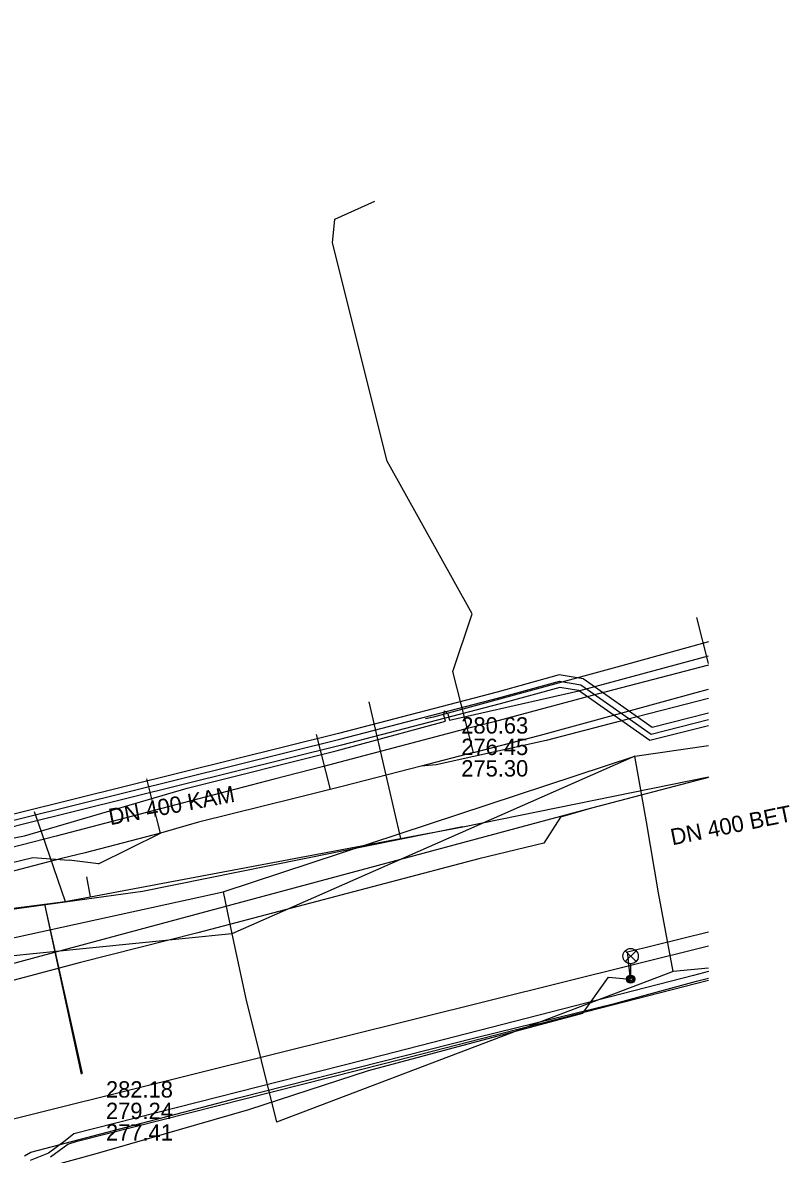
# Model space of a CAD drawing. Extents: x -599854 to -599675, y -1160809 to -1160543.
# Drawn here: x -599712.8 to -599675.3, y -1160609.7 to -1160554.4 of the extents above; entities that cross this region are included whole.
import ezdxf

# ---------------------------------------------------------------- set-up
doc = ezdxf.new("R2010")
doc.units = 0
for name, color, linetype in [('BKOM-ODVODNENI_trasa sítě', 7, 'Continuous'), ('BVK-JEDNOTNA_popisy', 7, 'Continuous'), ('BVK-JEDNOTNA_trasa sítě', 7, 'Continuous'), ('BVK-KANALIZACE_ vyřazená trasa sítě', 7, 'Continuous'), ('BVK-VODOVOD_trasa sítě', 7, 'Continuous'), ('BVK-VODOVOD_trasa zrušené sítě', 7, 'Continuous'), ('CETIN_kabel podzemní', 7, 'Continuous'), ('DESTOVA_trasa neprovozované sítě', 7, 'Continuous'), ('DPMB_kabel', 7, 'Continuous'), ('DPMB_kyneta', 7, 'Continuous'), ('DPMB_trolejové vedení-nosné lano', 7, 'Continuous'), ('DSP-JEDNOTNA-BVK_trasa sítě', 7, 'Continuous'), ('EON-NN_kabel', 7, 'Continuous'), ('EON-VN_kabel', 7, 'Continuous'), ('INNOGY-STL_trasa sítě', 7, 'Continuous'), ('JEDNOTNA_trasa neprovozované sítě', 7, 'Continuous'), ('QUANTCOM_kabel', 7, 'Continuous'), ('TSB_kabel VO', 7, 'Continuous'), ('TSB_lampy VO', 7, 'Continuous')]:
    doc.layers.add(name, color=color, linetype=linetype)

msp = doc.modelspace()

# ---------------------------------------------------------------- linework, layer by layer
at = {"layer": 'BKOM-ODVODNENI_trasa sítě'}
for points in [[(-599728.85, -1160599.72), (-599710.68, -1160597.38)], [(-599709.827, -1160605.79), (-599711.67, -1160597.51)]]:
    msp.add_lwpolyline(points, dxfattribs=at)
at = {"layer": 'BVK-JEDNOTNA_popisy'}
for p, q in [((-599691.309, -1160589.819), (-599691.309, -1160589.819)), ((-599708.68, -1160607.611), (-599708.68, -1160607.611))]:
    msp.add_line(p, q, dxfattribs=at)
at = {"layer": 'BVK-JEDNOTNA_trasa sítě'}
msp.add_line((-599691.23, -1160593.72), (-599679.2237, -1160591.2908), dxfattribs=at)
msp.add_lwpolyline([(-599710.68, -1160597.38), (-599709.45, -1160597.149), (-599694.277, -1160594.293), (-599691.23, -1160593.72)], dxfattribs=at)
at = {"layer": 'BVK-KANALIZACE_ vyřazená trasa sítě'}
for p, q in [((-599706.89, -1160596.87), (-599691.244, -1160593.711)), ((-599747.65, -1160602.53), (-599706.89, -1160596.87))]:
    msp.add_line(p, q, dxfattribs=at)
at = {"layer": 'BVK-VODOVOD_trasa sítě'}
msp.add_line((-599679.2237, -1160585.7449), (-599679.795, -1160583.492), dxfattribs=at)
for points in [[(-599679.2237, -1160591.3119), (-599684.94, -1160592.81)], [(-599684.94, -1160592.81), (-599686.46, -1160593.25), (-599687.27, -1160594.52), (-599690.45, -1160595.29), (-599704.19, -1160598.9), (-599709.92, -1160600.36), (-599718.2, -1160602.56), (-599719.28, -1160602.87), (-599719.633, -1160602.967)]]:
    msp.add_lwpolyline(points, dxfattribs=at)
at = {"layer": 'BVK-VODOVOD_trasa zrušené sítě'}
for points in [[(-599684.94, -1160592.81), (-599720.55, -1160602.37), (-599722.14, -1160601.43), (-599723.128, -1160597.158), (-599723.241, -1160596.669)], [(-599679.2237, -1160599.5579), (-599732.933, -1160612.912), (-599785.657, -1160621.012)]]:
    msp.add_lwpolyline(points, dxfattribs=at)
at = {"layer": 'CETIN_kabel podzemní'}
for points in [[(-599690.71, -1160590.1), (-599691.73, -1160586.14), (-599690.78, -1160583.31), (-599694.94, -1160575.86), (-599697.61, -1160565.18), (-599697.49, -1160564.02), (-599695.54, -1160563.15)], [(-599747.4, -1160585.47), (-599742.37, -1160594.32), (-599740.56, -1160595.49), (-599738.44, -1160596.21), (-599736.55, -1160596.84), (-599734.39, -1160596.99), (-599728.89, -1160596.5), (-599727.72, -1160596.19), (-599723.67, -1160595.52), (-599720.71, -1160596.76), (-599718.38, -1160596.71), (-599712.25, -1160595.23), (-599710.48, -1160595.36)], [(-599690.71, -1160590.1), (-599687.5, -1160589.27), (-599683.69, -1160588.22), (-599679.83, -1160587.16), (-599679.2237, -1160586.9936)], [(-599679.2237, -1160587.4478), (-599683.28, -1160588.5), (-599687.16, -1160589.5), (-599692.53, -1160590.69), (-599693.27, -1160590.76)], [(-599698.4, -1160589.21), (-599697.72, -1160591.9)], [(-599690.71, -1160590.1), (-599693.27, -1160590.76)], [(-599693.27, -1160590.76), (-599697.14, -1160591.76), (-599697.72, -1160591.9)], [(-599706.2, -1160593.33), (-599706.69, -1160591.38)], [(-599697.72, -1160591.9), (-599699.35, -1160592.31)], [(-599699.35, -1160592.31), (-599704.15, -1160593.5), (-599706.01, -1160594.04)], [(-599706.01, -1160594.04), (-599706.2, -1160593.33)], [(-599706.01, -1160594.04), (-599709.69, -1160594.99)], [(-599709.04, -1160595.54), (-599706.01, -1160594.04)], [(-599709.69, -1160594.99), (-599710.85, -1160595.28)], [(-599710.85, -1160595.28), (-599714.54, -1160596.23), (-599714.84, -1160596.6)], [(-599709.04, -1160595.54), (-599710.48, -1160595.36)]]:
    msp.add_lwpolyline(points, dxfattribs=at)
at = {"layer": 'DESTOVA_trasa neprovozované sítě'}
for p, q in [((-599709.635, -1160596.166), (-599709.45, -1160597.149)), ((-599709.87, -1160605.81), (-599711.672, -1160597.508))]:
    msp.add_line(p, q, dxfattribs=at)
msp.add_lwpolyline([(-599728.85, -1160599.72), (-599711.672, -1160597.508), (-599710.68, -1160597.38)], dxfattribs=at)
at = {"layer": 'DPMB_kabel'}
for points in [[(-599679.2237, -1160588.1676), (-599681.97, -1160588.865), (-599685.344, -1160586.495), (-599686.527, -1160586.303), (-599689.558, -1160587.14), (-599697.314, -1160589.159), (-599712.863, -1160593.019), (-599718.483, -1160594.441), (-599721.294, -1160594.539), (-599722.781, -1160593.351), (-599724.035, -1160587.852), (-599724.405, -1160585.594), (-599725.644, -1160579.901), (-599728.628, -1160572.9), (-599732.573, -1160567.596), (-599737.293, -1160564.609), (-599740.184, -1160563.956), (-599742.967, -1160562.458), (-599745.93, -1160559.394)], [(-599679.2237, -1160588.1676), (-599681.97, -1160588.865), (-599685.344, -1160586.495), (-599686.527, -1160586.303), (-599689.558, -1160587.14), (-599697.314, -1160589.159), (-599712.863, -1160593.019), (-599718.483, -1160594.441), (-599721.294, -1160594.539), (-599722.781, -1160593.351), (-599724.035, -1160587.852), (-599724.405, -1160585.594), (-599725.644, -1160579.901), (-599728.628, -1160572.9), (-599732.573, -1160567.596), (-599737.293, -1160564.609), (-599740.184, -1160563.956), (-599742.967, -1160562.458), (-599745.93, -1160559.394)], [(-599746.11, -1160559.64), (-599743.15, -1160562.7), (-599740.29, -1160564.24), (-599737.41, -1160564.89), (-599732.78, -1160567.82), (-599728.89, -1160573.05), (-599725.931, -1160579.993), (-599724.7, -1160585.65), (-599724.33, -1160587.91), (-599723.05, -1160593.52), (-599721.395, -1160594.843), (-599718.44, -1160594.74), (-599712.79, -1160593.31), (-599697.24, -1160589.45), (-599689.48, -1160587.43), (-599686.51, -1160586.61), (-599685.46, -1160586.78), (-599682.03, -1160589.19), (-599679.2237, -1160588.477)], [(-599746.11, -1160559.64), (-599743.15, -1160562.7), (-599740.29, -1160564.24), (-599737.41, -1160564.89), (-599732.78, -1160567.82), (-599728.89, -1160573.05), (-599725.931, -1160579.993), (-599724.7, -1160585.65), (-599724.33, -1160587.91), (-599723.05, -1160593.52), (-599721.395, -1160594.843), (-599718.44, -1160594.74), (-599712.79, -1160593.31), (-599697.24, -1160589.45), (-599689.48, -1160587.43), (-599686.51, -1160586.61), (-599685.46, -1160586.78), (-599682.03, -1160589.19), (-599679.2237, -1160588.477)]]:
    msp.add_lwpolyline(points, dxfattribs=at)
at = {"layer": 'DPMB_kyneta'}
msp.add_lwpolyline([(-599679.2237, -1160588.7865), (-599682.09, -1160589.515), (-599685.576, -1160587.065), (-599686.493, -1160586.917), (-599689.402, -1160587.72), (-599697.166, -1160589.741), (-599712.717, -1160593.601), (-599718.397, -1160595.039), (-599721.496, -1160595.147), (-599723.319, -1160593.689), (-599724.625, -1160587.968), (-599724.995, -1160585.706), (-599726.218, -1160580.085), (-599729.152, -1160573.2), (-599732.987, -1160568.044), (-599737.527, -1160565.171), (-599740.396, -1160564.524), (-599743.333, -1160562.942), (-599746.29, -1160559.886), (-599753.886, -1160556.123), (-599765.587, -1160554.421), (-599775.611, -1160554.72)], dxfattribs=at)
at = {"layer": 'DPMB_trolejové vedení-nosné lano'}
for points in [[(-599682.83, -1160590.28), (-599679.2237, -1160589.7461)], [(-599702.95, -1160596.9), (-599682.83, -1160590.28)], [(-599682.83, -1160590.28), (-599702.52, -1160598.95)], [(-599682.25, -1160593.48), (-599682.83, -1160590.28)], [(-599681.66, -1160596.96), (-599682.25, -1160593.48)], [(-599715.84, -1160599.73), (-599702.95, -1160596.9)], [(-599702.95, -1160596.9), (-599702.52, -1160598.95)], [(-599680.95, -1160600.79), (-599681.66, -1160596.96)], [(-599702.52, -1160598.95), (-599716.14, -1160600.32)], [(-599702.52, -1160598.95), (-599701.84, -1160602.14)], [(-599680.95, -1160600.79), (-599700.35, -1160608.16)], [(-599679.2237, -1160600.6346), (-599680.95, -1160600.79)], [(-599701.84, -1160602.14), (-599700.35, -1160608.16)]]:
    msp.add_lwpolyline(points, dxfattribs=at)
at = {"layer": 'DSP-JEDNOTNA-BVK_trasa sítě'}
for p, q in [((-599728.85, -1160599.72), (-599711.672, -1160597.508)), ((-599711.672, -1160597.508), (-599710.68, -1160597.38)), ((-599709.87, -1160605.81), (-599711.672, -1160597.508))]:
    msp.add_line(p, q, dxfattribs=at)
at = {"layer": 'EON-NN_kabel'}
for points in [[(-599721.503, -1160575.197), (-599722.223, -1160575.341), (-599722.478, -1160575.392), (-599722.519, -1160575.475), (-599722.553, -1160575.544), (-599722.991, -1160576.436), (-599721.384, -1160580.851), (-599721.229, -1160581.473), (-599721.165, -1160581.729), (-599719.933, -1160586.674), (-599717.724, -1160594.352), (-599717.574, -1160594.841), (-599716.94, -1160594.98), (-599716.085, -1160594.816), (-599712.67, -1160594.16), (-599704.71, -1160591.83), (-599697.42, -1160590.02), (-599692.077, -1160588.556), (-599692.166, -1160588.271), (-599692.13, -1160588.05), (-599691.975, -1160588.211), (-599691.882, -1160588.508), (-599685.56, -1160587.08), (-599679.2237, -1160585.3638)], [(-599679.2237, -1160600.8053), (-599679.957, -1160600.999), (-599695.12, -1160604.889), (-599710.244, -1160608.724), (-599710.669, -1160609.069), (-599711.488, -1160609.671)], [(-599711.392, -1160609.849), (-599710.551, -1160609.231), (-599710.082, -1160609.086), (-599695.021, -1160605.277), (-599679.855, -1160601.386), (-599679.2237, -1160601.2192)], [(-599711.488, -1160609.671), (-599712.388, -1160610.038)]]:
    msp.add_lwpolyline(points, dxfattribs=at)
at = {"layer": 'EON-VN_kabel'}
msp.add_lwpolyline([(-599712.66, -1160609.8), (-599712.36, -1160609.62), (-599702.21, -1160606.98), (-599690.58, -1160604.02), (-599683.76, -1160602.34), (-599679.81, -1160601.27), (-599679.2237, -1160601.1246)], dxfattribs=at)
at = {"layer": 'INNOGY-STL_trasa sítě'}
msp.add_lwpolyline([(-599679.2237, -1160585.8252), (-599684.66, -1160587.24), (-599689.7, -1160588.59), (-599691.13, -1160588.96), (-599698.11, -1160590.8), (-599700.46, -1160591.4), (-599704.95, -1160592.57), (-599711.11, -1160594.18), (-599720.96, -1160596.71), (-599722.2, -1160597.03)], dxfattribs=at)
at = {"layer": 'JEDNOTNA_trasa neprovozované sítě'}
for p, q in [((-599695.832, -1160587.618), (-599694.277, -1160594.293)), ((-599712.194, -1160592.977), (-599712.003, -1160593.533)), ((-599712.003, -1160593.533), (-599710.68, -1160597.38))]:
    msp.add_line(p, q, dxfattribs=at)
at = {"layer": 'QUANTCOM_kabel'}
msp.add_lwpolyline([(-599679.2237, -1160584.6864), (-599683.52, -1160585.87), (-599692.66, -1160588.37), (-599693.06, -1160588.45)], dxfattribs=at)
at = {"layer": 'TSB_kabel VO'}
for points in [[(-599683.03, -1160601.17), (-599683.18, -1160599.83), (-599679.2237, -1160598.8615)], [(-599712.85, -1160612.2), (-599712.04, -1160611.97), (-599712.419, -1160610.595), (-599709.21, -1160609.71), (-599701.69, -1160607.54), (-599695.84, -1160605.63), (-599685.36, -1160602.84), (-599684.11, -1160601.08), (-599683.03, -1160601.17)]]:
    msp.add_lwpolyline(points, dxfattribs=at)
at = {"layer": 'TSB_lampy VO'}
for p, q in [((-599683.295, -1160600.31), (-599682.765, -1160599.78)), ((-599683.295, -1160599.78), (-599682.765, -1160600.31)), ((-599683.295, -1160600.31), (-599682.765, -1160599.78)), ((-599683.295, -1160599.78), (-599682.765, -1160600.31)), ((-599683.03, -1160600.42), (-599683.03, -1160601.17)), ((-599683.03, -1160600.42), (-599683.03, -1160601.17))]:
    msp.add_line(p, q, dxfattribs=at)
for centre, radius in [((-599683.03, -1160600.045), 0.375), ((-599683.03, -1160600.045), 0.375), ((-599683.03, -1160601.17), 0.2), ((-599683.03, -1160601.17), 0.2), ((-599683.03, -1160601.17), 0.1445), ((-599683.03, -1160601.17), 0.1445), ((-599683.03, -1160601.17), 0.0876), ((-599683.03, -1160601.17), 0.0876)]:
    msp.add_circle(centre, radius, dxfattribs=at)

# ---------------------------------------------------------------- texts
at = {"layer": 'BVK-JEDNOTNA_popisy'}
for s, p in [('280.63', (-599691.309, -1160589.169)), ('276.45', (-599691.309, -1160590.219)), ('275.30', (-599691.309, -1160591.269)), ('282.18', (-599708.68, -1160606.961)), ('279.24', (-599708.68, -1160608.011)), ('277.41', (-599708.68, -1160609.061))]:
    msp.add_text(s, height=0.8, dxfattribs=at).set_placement(p)
for s, rotation, p in [('DN 400 KAM', 10.657, (-599708.468, -1160593.649)), ('DN 400 BET', 11.43804, (-599680.99, -1160594.634))]:
    msp.add_text(s, height=0.8, rotation=rotation, dxfattribs=at).set_placement(p)

doc.saveas('drawing.dxf')
